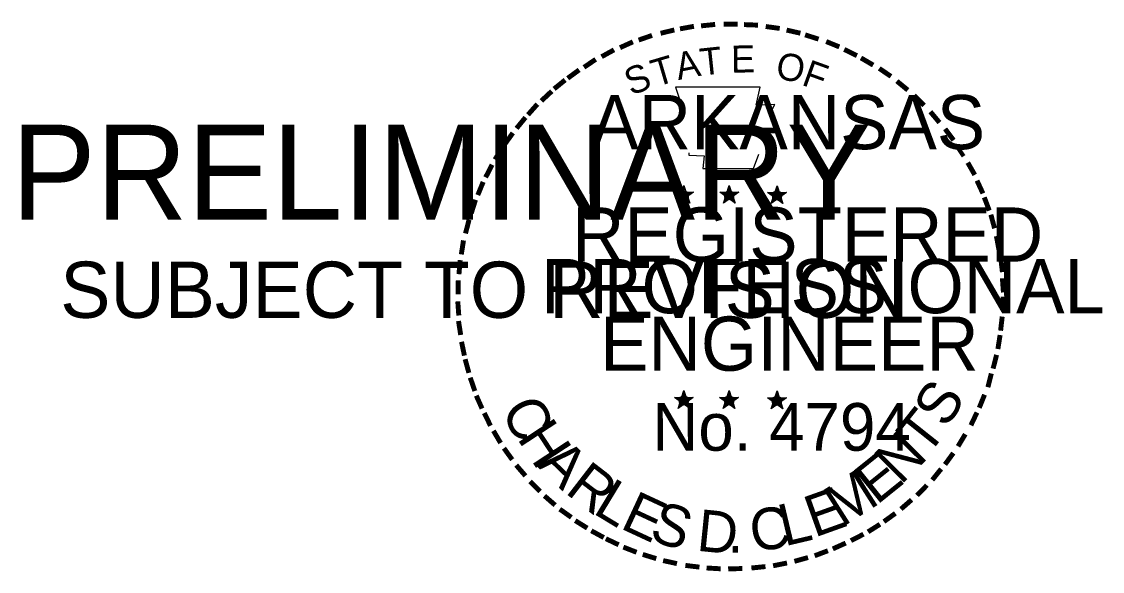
# Model space of a CAD drawing. Extents: x 3953 to 7490, y 10000 to 12548.
# Drawn here: x 5459.3 to 5658.7, y 12446.9 to 12548.4 of the extents above; entities that cross this region are included whole.
import ezdxf

# ---------------------------------------------------------------- set-up
doc = ezdxf.new("R2010")
doc.units = 0
doc.layers.add('STAMP_PE_FOSTER-SIGNATURE', color=7, linetype='Continuous')
doc.layers.add('STAMP_PE_SEAL-INFO', color=7, linetype='Continuous')

msp = doc.modelspace()

# ---------------------------------------------------------------- linework, layer by layer
at = {"layer": 'STAMP_PE_FOSTER-SIGNATURE'}
for p, q in [((5581.53, 12518.18), (5581.33, 12516.92)), ((5581.53, 12516.35), (5581.53, 12518.18)), ((5581.53, 12518.18), (5581.78, 12516.93)), ((5589.88, 12518.18), (5589.68, 12516.92)), ((5589.88, 12516.35), (5589.88, 12518.18)), ((5589.88, 12518.18), (5590.13, 12516.93)), ((5598.7, 12518.12), (5598.5, 12516.86)), ((5598.7, 12516.29), (5598.7, 12518.12)), ((5598.7, 12518.12), (5598.95, 12516.87)), ((5579.79, 12516.91), (5581.53, 12516.35)), ((5579.79, 12516.91), (5581.05, 12516.68)), ((5579.79, 12516.91), (5580.97, 12516.3)), ((5580.45, 12514.87), (5581.53, 12516.35)), ((5580.45, 12514.87), (5581.08, 12516.09)), ((5580.45, 12514.87), (5581.52, 12515.95)), ((5582.6, 12514.87), (5581.52, 12515.94)), ((5583.27, 12516.91), (5581.53, 12516.35)), ((5582.6, 12514.87), (5581.53, 12516.35)), ((5583.27, 12516.91), (5581.84, 12516.66)), ((5582.6, 12514.87), (5581.91, 12516.32)), ((5583.27, 12516.91), (5582.25, 12516.4)), ((5588.14, 12516.91), (5589.88, 12516.35)), ((5588.14, 12516.91), (5589.4, 12516.68)), ((5588.14, 12516.91), (5589.32, 12516.3)), ((5588.8, 12514.87), (5589.88, 12516.35)), ((5588.8, 12514.87), (5589.43, 12516.09)), ((5588.8, 12514.87), (5589.87, 12515.95)), ((5590.95, 12514.87), (5589.87, 12515.94)), ((5591.62, 12516.91), (5589.88, 12516.35)), ((5590.95, 12514.87), (5589.88, 12516.35)), ((5591.62, 12516.91), (5590.19, 12516.66)), ((5590.95, 12514.87), (5590.26, 12516.32)), ((5591.62, 12516.91), (5590.6, 12516.4)), ((5596.96, 12516.85), (5598.7, 12516.29)), ((5596.96, 12516.85), (5598.22, 12516.62)), ((5596.96, 12516.85), (5598.14, 12516.24)), ((5597.62, 12514.81), (5598.7, 12516.29)), ((5597.62, 12514.81), (5598.25, 12516.03)), ((5597.62, 12514.81), (5598.69, 12515.89)), ((5599.77, 12514.81), (5598.69, 12515.88)), ((5600.44, 12516.85), (5598.7, 12516.29)), ((5599.77, 12514.81), (5598.7, 12516.29)), ((5600.44, 12516.85), (5599.01, 12516.6)), ((5599.77, 12514.81), (5599.08, 12516.26)), ((5600.44, 12516.85), (5599.42, 12516.34)), ((5581.51, 12480.31), (5581.31, 12479.05)), ((5581.51, 12478.49), (5581.51, 12480.31)), ((5581.51, 12480.31), (5581.76, 12479.06)), ((5589.86, 12480.31), (5589.65, 12479.05)), ((5589.86, 12478.49), (5589.86, 12480.31)), ((5589.86, 12480.31), (5590.1, 12479.06)), ((5598.69, 12480.26), (5598.49, 12479)), ((5598.69, 12478.44), (5598.69, 12480.26)), ((5598.69, 12480.26), (5598.94, 12479.01)), ((5579.77, 12479.04), (5581.51, 12478.49)), ((5579.77, 12479.04), (5581.03, 12478.82)), ((5579.77, 12479.04), (5580.95, 12478.43)), ((5580.43, 12477), (5581.51, 12478.49)), ((5580.43, 12477), (5581.06, 12478.22)), ((5580.43, 12477), (5581.5, 12478.09)), ((5582.58, 12477), (5581.5, 12478.07)), ((5583.25, 12479.04), (5581.51, 12478.49)), ((5582.58, 12477), (5581.51, 12478.49)), ((5583.25, 12479.04), (5581.82, 12478.8)), ((5582.58, 12477), (5581.89, 12478.46)), ((5583.25, 12479.04), (5582.23, 12478.53)), ((5588.11, 12479.04), (5589.86, 12478.49)), ((5588.11, 12479.04), (5589.38, 12478.82)), ((5588.11, 12479.04), (5589.3, 12478.43)), ((5588.78, 12477), (5589.86, 12478.49)), ((5588.78, 12477), (5589.41, 12478.22)), ((5588.78, 12477), (5589.85, 12478.09)), ((5590.92, 12477), (5589.85, 12478.07)), ((5591.59, 12479.04), (5589.86, 12478.49)), ((5590.92, 12477), (5589.86, 12478.49)), ((5591.59, 12479.04), (5590.16, 12478.8)), ((5590.92, 12477), (5590.24, 12478.46)), ((5591.59, 12479.04), (5590.57, 12478.53)), ((5596.95, 12478.99), (5598.69, 12478.44)), ((5596.95, 12478.99), (5598.21, 12478.77)), ((5596.95, 12478.99), (5598.13, 12478.38)), ((5597.61, 12476.95), (5598.69, 12478.44)), ((5597.61, 12476.95), (5598.24, 12478.17)), ((5597.61, 12476.95), (5598.68, 12478.04)), ((5599.76, 12476.95), (5598.68, 12478.02)), ((5600.43, 12478.99), (5598.69, 12478.44)), ((5599.76, 12476.95), (5598.69, 12478.44)), ((5600.43, 12478.99), (5599, 12478.75)), ((5599.76, 12476.95), (5599.07, 12478.41)), ((5600.43, 12478.99), (5599.41, 12478.48))]:
    msp.add_line(p, q, dxfattribs=at)
for points in [[(5579.99, 12536.3), (5581.34, 12532.16)], [(5597.55, 12531.69), (5598.26, 12533.11), (5594.83, 12532.99), (5595.57, 12536.3), (5579.99, 12536.3)], [(5582.45, 12524.18), (5582.45, 12523.75), (5585.27, 12523.65), (5585, 12521.29), (5594.35, 12521.29), (5595.35, 12523.97)], [(5581.53, 12518.18), (5582.6, 12514.87), (5579.79, 12516.91), (5583.27, 12516.91), (5580.45, 12514.87), (5581.53, 12518.18)], [(5589.88, 12518.18), (5590.95, 12514.87), (5588.14, 12516.91), (5591.62, 12516.91), (5588.8, 12514.87), (5589.88, 12518.18)], [(5598.7, 12518.12), (5599.77, 12514.81), (5596.96, 12516.85), (5600.44, 12516.85), (5597.62, 12514.81), (5598.7, 12518.12)], [(5581.51, 12480.31), (5582.58, 12477), (5579.77, 12479.04), (5583.25, 12479.04), (5580.43, 12477), (5581.51, 12480.31)], [(5589.86, 12480.31), (5590.92, 12477), (5588.11, 12479.04), (5591.59, 12479.04), (5588.78, 12477), (5589.86, 12480.31)], [(5598.69, 12480.26), (5599.76, 12476.95), (5596.95, 12478.99), (5600.43, 12478.99), (5597.61, 12476.95), (5598.69, 12480.26)]]:
    msp.add_lwpolyline(points, dxfattribs=at)
for centre, radius in [((5581.52, 12516.35), 0.861), ((5581.52, 12516.35), 0.723), ((5581.52, 12516.35), 0.579), ((5581.52, 12516.35), 0.495), ((5581.52, 12516.35), 0.374), ((5581.52, 12516.35), 0.248), ((5581.52, 12516.35), 0.148), ((5589.87, 12516.35), 0.861), ((5589.87, 12516.35), 0.723), ((5589.87, 12516.35), 0.579), ((5589.87, 12516.35), 0.495), ((5589.87, 12516.35), 0.374), ((5589.87, 12516.35), 0.248), ((5589.87, 12516.35), 0.148), ((5598.69, 12516.29), 0.861), ((5598.69, 12516.29), 0.723), ((5598.69, 12516.29), 0.579), ((5598.69, 12516.29), 0.495), ((5598.69, 12516.29), 0.374), ((5598.69, 12516.29), 0.248), ((5598.69, 12516.29), 0.148), ((5581.5, 12478.48), 0.861), ((5581.5, 12478.48), 0.723), ((5581.5, 12478.48), 0.579), ((5581.5, 12478.48), 0.495), ((5581.5, 12478.48), 0.374), ((5581.5, 12478.48), 0.248), ((5581.5, 12478.48), 0.148), ((5589.85, 12478.48), 0.861), ((5589.85, 12478.48), 0.723), ((5589.85, 12478.48), 0.579), ((5589.85, 12478.48), 0.495), ((5589.85, 12478.48), 0.374), ((5589.85, 12478.48), 0.248), ((5589.85, 12478.48), 0.148), ((5598.68, 12478.43), 0.861), ((5598.68, 12478.43), 0.723), ((5598.68, 12478.43), 0.579), ((5598.68, 12478.43), 0.495), ((5598.68, 12478.43), 0.374), ((5598.68, 12478.43), 0.248), ((5598.68, 12478.43), 0.148)]:
    msp.add_circle(centre, radius, dxfattribs=at)

# ---------------------------------------------------------------- texts
for s, height, rotation, p in [('-', 8, 10.2193, (5580.87, 12543.95)), ('-', 8, 5.8968, (5584.52, 12544.5)), ('-', 8, 0.1862, (5588.38, 12544.86)), ('-', 8, 357.743, (5591.99, 12544.79)), ('-', 8, 352.1617, (5595.71, 12544.51)), ('-', 8, 19.1761, (5573.73, 12541.93)), ('-', 8, 13.6302, (5577.48, 12543.14)), ('-', 8, 347.2049, (5599.31, 12543.94)), ('-', 8, 342.3362, (5602.48, 12543.17)), ('-', 8, 28.7918, (5567.4, 12539)), ('-', 8, 24.3072, (5570.56, 12540.59)), ('T', 5, 6.0228, (5584.71, 12538.43)), ('E', 5, 0.8323, (5590.24, 12538.98)), ('-', 8, 337.8551, (5606.16, 12542.05)), ('-', 8, 334.1211, (5609.31, 12540.7)), ('-', 8, 34.0636, (5564.41, 12537.15)), ('T', 5, 16.4036, (5576.34, 12536.34)), ('A', 5, 11.2132, (5580.47, 12537.6)), ('O', 5, 350.4515, (5598.26, 12537.93)), ('-', 8, 329.6409, (5612.21, 12539.28)), ('-', 8, 36.2317, (5561.52, 12535.18)), ('S', 5, 21.594, (5571.77, 12534.69)), ('F', 5, 340.0707, (5603.03, 12536.79)), ('-', 8, 325.8627, (5615.42, 12537.48)), ('-', 8, 38.9507, (5559.14, 12533.29)), ('-', 8, 320.5297, (5618.47, 12535.35)), ('-', 8, 42.9622, (5556.98, 12531.2)), ('-', 8, 48.4231, (5554.74, 12528.81)), ('-', 8, 315.5786, (5621.47, 12532.91)), ('-', 8, 309.8797, (5624.31, 12530.16)), ('-', 8, 50.6142, (5552.72, 12526.38)), ('-', 8, 54.2325, (5550.66, 12523.55)), ('-', 8, 306.6522, (5626.94, 12527.15)), ('-', 7, 303.6753, (5629.37, 12524.31)), ('-', 8, 58.0706, (5549.03, 12520.91)), ('-', 8, 62.8713, (5547.47, 12517.84)), ('-', 8, 299.6684, (5630.96, 12521.27)), ('-', 8, 67.7743, (5546.17, 12514.79)), ('-', 8, 294.6628, (5632.58, 12518.21)), ('-', 8, 72.3945, (5545.08, 12511.64)), ('-', 8, 290.5728, (5633.87, 12515.33)), ('-', 8, 75.461, (5544.09, 12508.07)), ('-', 8, 285.1233, (5635.04, 12512.43)), ('-', 8, 81.2013, (5543.43, 12504.5)), ('-', 8, 280.5493, (5636.04, 12508.72)), ('-', 8, 85.1863, (5543.05, 12501.05)), ('-', 8, 276.5962, (5636.85, 12504.88)), ('-', 8, 89.0622, (5542.93, 12497.54)), ('-', 8, 274.3301, (5637.15, 12501.27)), ('-', 8, 269.9407, (5637.32, 12498.11)), ('-', 8, 94.1959, (5543.1, 12493.92)), ('-', 8, 263.5172, (5637.22, 12494.78)), ('-', 8, 98.9479, (5543.46, 12490.58)), ('-', 8, 260.9953, (5636.87, 12491.51)), ('-', 8, 101.7149, (5544.14, 12486.92)), ('-', 8, 105.4578, (5544.95, 12483.94)), ('-', 8, 255.7626, (5636.32, 12488.12)), ('-', 8, 109.0874, (5546.02, 12480.79)), ('S', 7.7, 57.878, (5629.97, 12473.15)), ('-', 8, 255.7626, (5635.36, 12484.68)), ('-', 8, 247.8887, (5634.3, 12481.15)), ('-', 8, 114.0643, (5547.29, 12477.81)), ('C', 7.7, 296.9133, (5547.66, 12476.77)), ('-', 8, 115.7289, (5548.82, 12474.72)), ('T', 7.7, 51.5114, (5626.33, 12467.94)), ('-', 8, 244.6197, (5632.99, 12478.01)), ('H', 7.7, 303.2799, (5550.61, 12471.56)), ('-', 8, 120.4471, (5550.6, 12471.79)), ('N', 7.7, 45.1449, (5621.53, 12462.73)), ('-', 8, 239.0712, (5631.02, 12474.25)), ('-', 8, 125.8934, (5552.62, 12468.98)), ('A', 7.7, 316.013, (5554.25, 12466.44)), ('E', 7.7, 38.7783, (5617.08, 12459.08)), ('-', 8, 233.8452, (5629.01, 12470.98)), ('-', 8, 130.7181, (5554.93, 12466.22)), ('R', 7.7, 322.3796, (5559.38, 12461.53)), ('-', 8, 231.2538, (5626.86, 12468.15)), ('-', 8, 134.2238, (5557.51, 12463.5)), ('L', 7.7, 328.7461, (5564.51, 12457.78)), ('M', 7.7, 32.4117, (5610.68, 12455.01)), ('E', 7.7, 19.6786, (5605.57, 12453.13)), ('-', 8, 225.7653, (5624.46, 12465.33)), ('-', 8, 138.9338, (5560.14, 12461.18)), ('E', 7.7, 335.1127, (5569.54, 12454.98)), ('-', 8, 221.0851, (5621.85, 12462.79)), ('-', 8, 144.6463, (5562.92, 12459.15)), ('S', 7.7, 341.4792, (5574.87, 12452.83)), ('D', 7.7, 354.2124, (5583.7, 12450.77)), ('C', 7.7, 6.9455, (5594.13, 12450.57)), ('L', 7.7, 13.3121, (5600.05, 12451.53)), ('-', 8, 215.7363, (5619.11, 12460.43)), ('-', 8, 148.0898, (5565.72, 12457.29)), ('-', 8, 212.2491, (5616.44, 12458.49)), ('-', 8, 151.5704, (5568.62, 12455.67)), ('-', 8, 207.3568, (5613.65, 12456.76)), ('-', 8, 154.6002, (5571.23, 12454.43)), ('-', 8, 158.5612, (5574.35, 12453.16)), ('-', 8, 204.2516, (5610.53, 12455.17)), ('-', 8, 162.7983, (5577.78, 12452.1)), ('.', 7.7, 0.5789, (5589.57, 12450.38)), ('-', 8, 195.4743, (5604.05, 12452.59)), ('-', 8, 200.7184, (5607.43, 12453.8)), ('-', 8, 167.5555, (5581.36, 12451.28)), ('-', 8, 173.1155, (5585.22, 12450.73)), ('-', 8, 176.5183, (5588.96, 12450.46)), ('-', 8, 181.5918, (5592.68, 12450.56)), ('-', 8, 185.8167, (5596.72, 12450.94)), ('-', 8, 191.2858, (5600.4, 12451.6))]:
    msp.add_text(s, height=height, rotation=rotation, dxfattribs=at).set_placement(p)
for s, height, p in [('ARKANSAS', 10, (5564.26, 12524.86)), ('REGISTERED', 10, (5560.87, 12504.11)), ('PROFESSIONAL', 10, (5555.13, 12494.59)), ('ENGINEER', 10, (5566.06, 12483.97)), ('No. 4794', 8.785, (5575.69, 12469.21))]:
    msp.add_text(s, height=height, dxfattribs=at).set_placement(p)
at = {"layer": 'STAMP_PE_SEAL-INFO'}
for s, height, p in [('PRELIMINARY', 17.5, (5457.41, 12511.88)), ('SUBJECT TO REVISION', 10.3756, (5466.46, 12493.73))]:
    msp.add_text(s, height=height, dxfattribs=at).set_placement(p)

doc.saveas('drawing.dxf')
